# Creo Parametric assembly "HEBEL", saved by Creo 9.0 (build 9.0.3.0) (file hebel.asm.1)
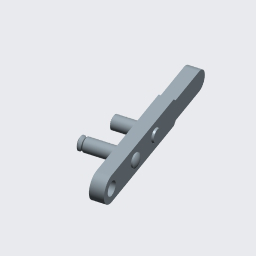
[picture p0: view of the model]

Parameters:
  ERSTELLER = "ARINDA"
  BENENNUNG = "XXX"
  TEILETYP = "K"

Other parameters: MASSE

Created from: ARINDA.ASM

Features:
  1. coordinate system "ACS0"
  2. datum plane "ADTM1", "A_RECHTS_Y-Z"
  3. datum plane "ADTM2", "A_OBEN_X-Z"
  4. datum plane "ADTM3", "A_VORNE_X-Y"
  5. datum axis "AA_X"
  6. datum axis "AA_2"
  7. datum axis "AA_Z"
  8. datum point "APNT0"
  9. component "HEBEL"
  10. component "ISO2338", "ISO2338A3X12.PRT"
  11. component "ISO2338-4M6X16"

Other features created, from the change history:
  datum axis "AA_1"
  datum plane "ADTM1"
  component "ISO2338A3X16.PRT"

Other named items: AA_Y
